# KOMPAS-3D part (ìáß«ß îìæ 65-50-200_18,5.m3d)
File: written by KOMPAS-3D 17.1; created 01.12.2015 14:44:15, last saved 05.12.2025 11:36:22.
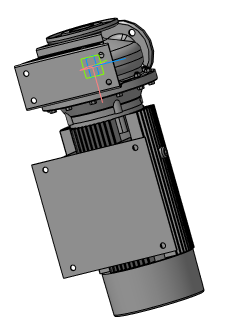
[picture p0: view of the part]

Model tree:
1. Операция без истории:4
